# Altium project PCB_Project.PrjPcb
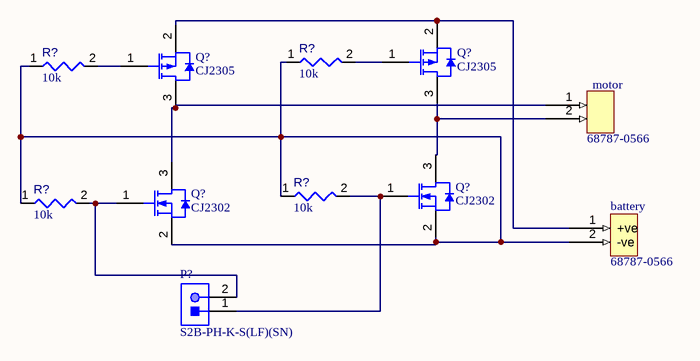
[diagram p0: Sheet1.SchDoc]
CAGE_CODE: ?????; CONTRACT_NUMBER: <CONTRACT NO>; DOC_NO_ASSY_DWG: <ASSY DWG NO>; DOC_NO_BOM: <BOM DOC NO>; DOC_NO_FAB_DWG: <FAB DWG NO>; DOC_NO_SCH_DWG: <SCH DWG NO>; PCB_2_DEC_TOL: +/-.01; PCB_3_DEC_TOL: +/-.010; PCB_ANG_TOL: +/-1/2; PCB_ASSEMBLY_NO: <PCB ASSY NO>; PCB_CHECKER: - -----; PCB_CHECKER_APP_DATE: --/--/----; PCB_DESIGNER: - -----; PCB_DESIGNER_APP_DATE: --/--/----; PCB_DWG_NO: <PCB DWG NO>; PCB_ENGINEER: - -----; PCB_ENGINEER_APP_DATE: --/--/----; PCB_PART_NUMBER: <PCB PN>; PCB_REV: A; SCH_REV: A
1 sheet, 11 parts. Net scope: global (net labels, ports and power ports of the same name join across sheets).
Board file: PCB1.PcbDoc

## Sheet Sheet1.SchDoc
size 431 x 279 mm; SheetNumber: 1; SheetTotal: 1; ENG_APP_DATE: --/--/--; DSN_APP_DATE: --/--/--; CHK_APP_DATE: --/--/--

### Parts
(Parts that share a designator on the sheet are numbered #1, #2 ... from top to bottom, then left to right.)
battery  68787-0566
motor  68787-0566
P?  S2B-PH-K-S(LF)(SN)  [JST-S2B-PH-K-S_V]
Q?#1  CJ2305  [JSCJ-SOT23-3_V]
Q?#2  CJ2305  [JSCJ-SOT23-3_V]
Q?#3  CJ2302  [JSCJ-SOT23-3_V]
Q?#4  CJ2302  [JSCJ-SOT23-3_V]
R?#1  value 10k  [RESC0402(1005)_L]  (hidden comment: 10KR2F)
R?#2  value 10k  [RESC0402(1005)_L]  (hidden comment: 10KR2F)
R?#3  value 10k  [RESC0402(1005)_L]  (hidden comment: 10KR2F)
R?#4  value 10k  [RESC0402(1005)_L]  (hidden comment: 10KR2F)

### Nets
Netbattery_1: battery.1(+ve) Q?#1.2(SOURCE) Q?#2.2(SOURCE)
Netbattery_2: battery.2(-ve) Q?#3.2(S) Q?#4.2(S) R?#1.1 R?#2.1 R?#3.1 R?#4.1
Netmotor_1: motor.1 Q?#1.3(DRAIN) Q?#4.3(D)
Netmotor_2: motor.2 Q?#2.3(DRAIN) Q?#3.3(D)
NetP?_1: P?.1 Q?#3.1(G) R?#3.2
NetP?_2: P?.2 Q?#4.1(G) R?#4.2
NetQ?#1_1: Q?#1.1(GATE) R?#1.2
NetQ?#2_1: Q?#2.1(GATE) R?#2.2

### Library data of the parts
battery motor = CMP-002-00071-2: Vga 15P (F) To 16P W/B Rosetta 2U Dell/Molex
P? = CMP-002-00030-2: Male Header, Pitch 2 mm, 1 x 2 Position, Height 4.8 mm, Tail Length 3.4 mm, -25 to 85 degC, RoHS, Bulk; Manufacturer: Japan Solderless Terminals
Q?#1 Q?#2 = CMP-013-00015-3: P-Channel Plastic Encapsulate MOSFET, 12 V, 4.1 A, 3-Pin SOT23, Tape and Reel; Manufacturer: Jiangsu Changjiang Electronics Technology; Package Version: Rev. E, 09/2009
Q?#3 Q?#4 = CMP-013-00014-3: N-Channe Plastic Encapsulate MOSFET, 20 V, 2.1 A, 3-Pin SOT23, Tape and Reel; Manufacturer: Jiangsu Changjiang Electronics Technology; Package Version: Rev. E, 09/2009
R?#1-R?#4 = CMP-009-00066-2: 10K 0.063W 1% 0402 (1005 Metric)  SMD; Power: 63mW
